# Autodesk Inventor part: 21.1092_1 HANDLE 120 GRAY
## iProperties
Created: 2007-03
Part Number: 21.1092_1 HANDLE 120 GRAY
Document SubType Name: Modeling
Designer: Andy Moles
Material: ABS Plastic
Mass: 45.1327 g
Surface Area: 162.805 cm^2
Volume: 42.578 cm^3
Density: 1.06 g/cm^3
Author: Andy Moles
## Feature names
1. Extrusion1
2. Extrusion2
3. Extrusion3
4. Extrusion4
5. Fillet1
6. Fillet2
7. Fillet3
